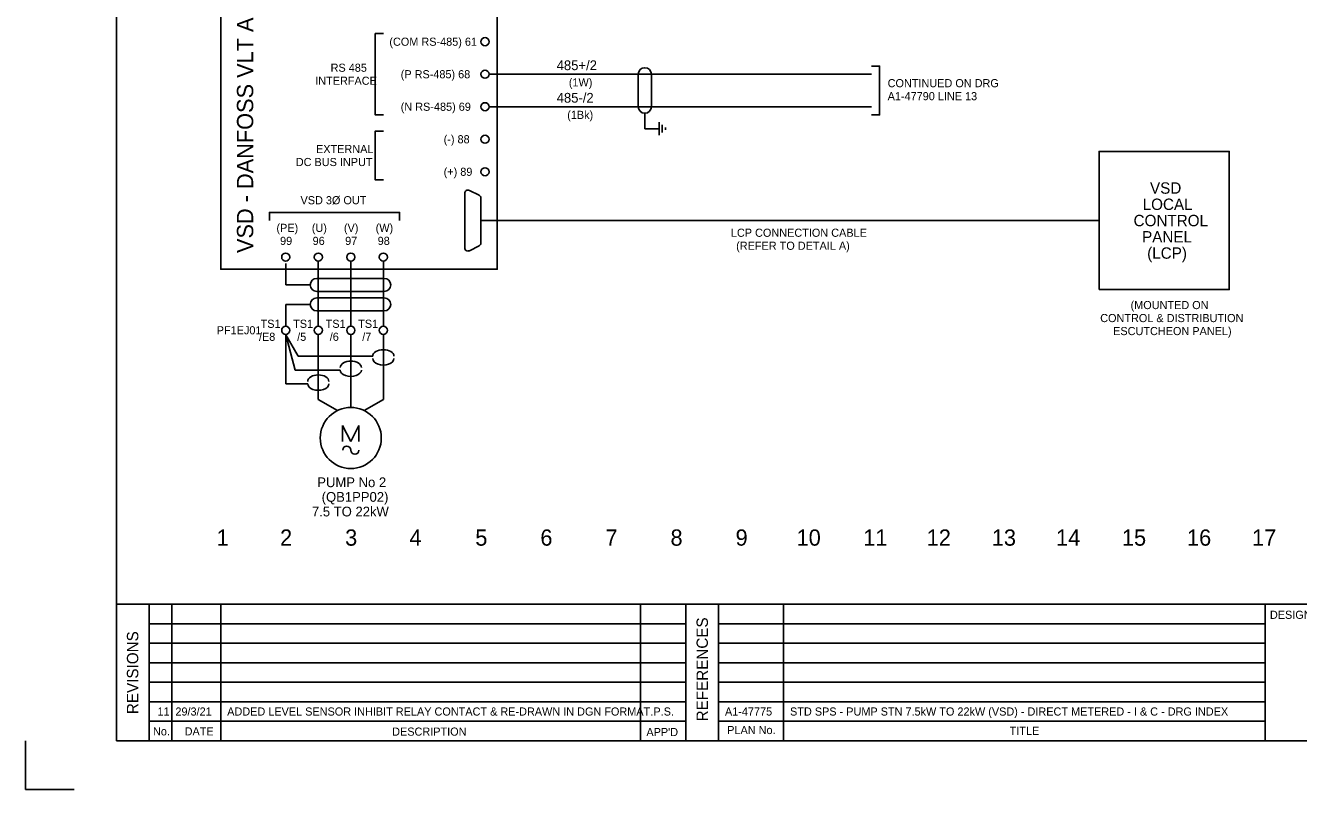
# Model space of a CAD drawing. Extents: x 0 to 841, y 0 to 594.
# Drawn here: x 0 to 391.3, y 0 to 235 of the extents above; entities that cross this region are included whole.
import ezdxf

# ---------------------------------------------------------------- set-up
doc = ezdxf.new("R2010")
doc.units = 0
for name, color, linetype in [('A1BORDER', 7, 'Continuous'), ('BASE', 7, 'Continuous'), ('Level 1', 7, 'Continuous'), ('Level 10', 7, 'Continuous'), ('Level 4', 7, 'Continuous'), ('Level 5', 7, 'Continuous'), ('Level 6', 7, 'Continuous'), ('Screen', 7, 'Continuous')]:
    doc.layers.add(name, color=color, linetype=linetype)

msp = doc.modelspace()

# ---------------------------------------------------------------- linework, layer by layer
at = {"layer": 'A1BORDER'}
for p, q in [((28, 581), (28, 15)), ((28, 57), (829, 57)), ((38, 15), (38, 57)), ((45, 15), (45, 57)), ((60, 15), (60, 57)), ((189, 15), (189, 57)), ((203, 15), (203, 57)), ((213, 15), (213, 57)), ((233, 15), (233, 57)), ((381, 15), (381, 57)), ((203, 51), (38, 51)), ((213, 51), (381, 51)), ((203, 45), (38, 45)), ((213, 45), (381, 45)), ((203, 39), (38, 39)), ((213, 39), (381, 39)), ((203, 33), (38, 33)), ((213, 33), (381, 33)), ((38, 27), (203, 27)), ((213, 27), (381, 27)), ((203, 21), (38, 21)), ((213, 21), (381, 21)), ((0, 0), (0, 15)), ((829, 15), (28, 15)), ((0, 0), (15, 0))]:
    msp.add_line(p, q, dxfattribs=at)
at = {"layer": 'BASE'}
for p, q in [((188.37, 220), (188.37, 210)), ((192.37, 220), (192.37, 210)), ((190.37, 208), (190.37, 203.25)), ((194.74, 203.25), (190.37, 203.25))]:
    msp.add_line(p, q, dxfattribs=at)
for centre, start, end in [((190.37, 220), 0, 180), ((190.37, 210), 180, 0)]:
    msp.add_arc(centre, 2, start, end, dxfattribs=at)
at = {"layer": 'Level 1'}
for p, q in [((136.45, 184.28), (139.45, 182.78)), ((135, 166.62), (135, 183.38)), ((140, 168.12), (140, 181.88)), ((140, 175), (330, 175)), ((136.45, 165.72), (139.45, 167.22)), ((90, 162.5), (90, 142.5)), ((100, 142.5), (100, 162.5)), ((110, 162.5), (110, 142.5)), ((90, 140), (90, 120)), ((100, 117.5), (100, 140)), ((110, 140), (110, 120))]:
    msp.add_line(p, q, dxfattribs=at)
for points in [[(60, 480), (145, 480), (145, 160), (60, 160)], [(330, 153.75), (370, 153.75), (370, 196.25), (330, 196.25)]]:
    msp.add_lwpolyline(points, close=True, dxfattribs=at)
for points in [[(110, 207.5), (107.5, 207.5), (107.5, 232.5), (110, 232.5)], [(260, 222.5), (262.5, 222.5), (262.5, 207.5), (260, 207.5)], [(110, 202.5), (107.5, 202.5), (107.5, 187.5), (110, 187.5)], [(75, 175), (75, 177.5), (115, 177.5), (115, 175)]]:
    msp.add_lwpolyline(points, dxfattribs=at)
for centre, start, end in [((136, 183.38), 63.4349, 180), ((139, 181.88), 0, 63.4349), ((136, 166.62), 180, 296.5651), ((139, 168.12), 296.5651, 360)]:
    msp.add_arc(centre, 1, start, end, dxfattribs=at)
at = {"layer": 'Level 10'}
for p, q in [((194.74, 201.25), (194.74, 205.25)), ((195.74, 202.05), (195.74, 204.45)), ((196.74, 202.85), (196.74, 203.65))]:
    msp.add_line(p, q, dxfattribs=at)
at = {"layer": 'Level 4'}
for p, q in [((97.49, 112), (100, 107)), ((97.49, 107), (97.49, 112)), ((100, 107), (102.51, 112)), ((102.51, 112), (102.51, 107))]:
    msp.add_line(p, q, dxfattribs=at)
for centre, radius in [((80, 163.75), 1.25), ((90, 163.75), 1.25), ((100, 163.75), 1.25), ((110, 163.75), 1.25), ((80, 141.25), 1.25), ((90, 141.25), 1.25), ((100, 141.25), 1.25), ((110, 141.25), 1.25), ((100, 108.12), 9.38)]:
    msp.add_circle(centre, radius, dxfattribs=at)
for centre, start, end in [((98.75, 104.38), 0, 180), ((101.25, 104.38), 180, 360)]:
    msp.add_arc(centre, 1.24, start, end, dxfattribs=at)
at = {"layer": 'Level 5'}
for p, q in [((90, 120), (95.89, 116.61)), ((110, 120), (104.11, 116.61))]:
    msp.add_line(p, q, dxfattribs=at)
for centre in [(141.25, 230), (141.25, 220), (141.25, 210), (141.25, 200), (141.25, 190)]:
    msp.add_circle(centre, 1.25, dxfattribs=at)
at = {"layer": 'Level 6'}
for p, q in [((142.5, 220), (260, 220)), ((142.5, 210), (260, 210))]:
    msp.add_line(p, q, dxfattribs=at)
at = {"layer": 'Screen'}
for p, q in [((80, 155.21), (80, 161.82)), ((89.52, 157.21), (110.27, 157.21)), ((80, 155.21), (87.52, 155.21)), ((89.52, 153.21), (110.27, 153.21)), ((80, 149.21), (87.52, 149.21)), ((80, 142.37), (80, 149.21)), ((89.52, 151.21), (110.27, 151.21)), ((89.52, 147.21), (110.27, 147.21)), ((80, 139.87), (82.9, 129.03)), ((80, 124.78), (80, 139.87)), ((80, 139.87), (83.8, 133.28)), ((83.8, 133.28), (106.75, 133.28)), ((82.9, 129.03), (96.75, 129.03)), ((80, 124.78), (86.75, 124.78))]:
    msp.add_line(p, q, dxfattribs=at)
for centre, start, end in [((89.52, 155.21), 90, 270), ((110.27, 155.21), 270, 90), ((89.52, 149.21), 90, 270), ((110.27, 149.21), 270, 90)]:
    msp.add_arc(centre, 2, start, end, dxfattribs=at)
for centre, start_param, end_param in [((110, 133.28), 3.141593, 6.283185), ((100, 129.78), 3.141593, 6.283185), ((110, 132.53), 0, 3.141593), ((90, 125.53), 3.141593, 6.283185), ((100, 129.03), 0, 3.141593), ((90, 124.78), 0, 3.141593)]:
    msp.add_ellipse(centre, major_axis=(-3.25, 0), ratio=0.615385, start_param=start_param, end_param=end_param, dxfattribs=at)

# ---------------------------------------------------------------- texts
at = {"layer": 'A1BORDER'}
for s, p in [('DESIGNED BY:', (382.5, 52.5)), ('No.', (39.21, 16.65)), ('DATE', (48.92, 16.65)), ('DESCRIPTION', (112.71, 16.57)), ("APP'D", (190.85, 16.44)), ('PLAN No.', (215.69, 17.06)), ('TITLE', (302.5, 16.81))]:
    msp.add_text(s, height=2.5, dxfattribs=at).set_placement(p)
for s, p in [('REFERENCES', (209.76, 20.96)), ('REVISIONS', (34.68, 23.2))]:
    msp.add_text(s, height=3.5, rotation=90, dxfattribs=at).set_placement(p)
at = {"layer": 'Level 1'}
msp.add_text('VSD - DANFOSS VLT AQUA FC 202', height=5, rotation=90, dxfattribs=at).set_placement((70, 165))
for s, height, p in [('(COM RS-485) 61', 2.5, (111.85, 228.75)), ('RS 485', 2.5, (93.79, 220.75)), ('INTERFACE', 2.5, (89.06, 216.75)), ('(P RS-485) 68', 2.5, (115.34, 218.75)), ('CONTINUED ON DRG', 2.5, (265, 216)), ('(N RS-485) 69', 2.5, (115.34, 208.75)), ('A1-47790 LINE 13', 2.5, (265, 212)), ('(-) 88', 2.5, (128.54, 198.75)), ('EXTERNAL', 2.5, (89.31, 195.75)), ('DC BUS INPUT', 2.5, (83.09, 191.75)), ('(+) 89', 2.5, (128.54, 188.75)), ('VSD', 3.5, (345.64, 183.25)), ('VSD 3Ø OUT', 2.5, (84.54, 180)), ('LOCAL', 3.5, (343.38, 178.25)), ('CONTROL', 3.5, (340.59, 173.25)), ('(PE)', 2.5, (77.14, 171.5)), ('(U)', 2.5, (88.01, 171.5)), ('(V)', 2.5, (97.88, 171.5)), ('(W)', 2.5, (107.64, 171.5)), ('LCP CONNECTION CABLE', 2.5, (216.82, 170)), ('99', 2.5, (78.26, 167.5)), ('96', 2.5, (88.26, 167.5)), ('97', 2.5, (98.26, 167.5)), ('98', 2.5, (108.26, 167.5)), ('(REFER TO DETAIL A)', 2.5, (218.44, 166)), ('PANEL', 3.5, (343.2, 168.25)), ('(LCP)', 3.5, (344.77, 163.25)), ('(MOUNTED ON', 2.5, (339.67, 147.76)), ('CONTROL & DISTRIBUTION', 2.5, (330.33, 143.76)), ('ESCUTCHEON PANEL)', 2.5, (334.31, 139.76)), ('PUMP No 2', 3, (89.69, 93)), ('(QB1PP02)', 3, (91.04, 88.5)), ('7.5 TO 22kW', 3, (88.05, 84)), ('1', 5, (58.76, 75)), ('2', 5, (78.26, 75)), ('3', 5, (98.26, 75)), ('4', 5, (118.01, 75)), ('5', 5, (138.26, 75)), ('6', 5, (158.26, 75)), ('7', 5, (178.26, 75)), ('8', 5, (198.26, 75)), ('9', 5, (218.26, 75)), ('10', 5, (237.01, 75)), ('11', 5, (257.51, 75)), ('12', 5, (277.01, 75)), ('13', 5, (297.01, 75)), ('14', 5, (316.77, 75)), ('15', 5, (337.01, 75)), ('16', 5, (357.01, 75)), ('17', 5, (377.01, 75)), ('11', 2.5, (40.57, 22.75)), ('29/3/21', 2.5, (46.09, 22.75)), ('ADDED LEVEL SENSOR INHIBIT RELAY CONTACT & RE-DRAWN IN DGN FORMAT.', 2.5, (62, 22.75)), ('P.S.', 2.5, (193.02, 22.75)), ('A1-47775', 2.5, (215, 22.75)), ('STD SPS - PUMP STN 7.5kW TO 22kW (VSD) - DIRECT METERED - I & C - DRG INDEX', 2.5, (235, 22.75))]:
    msp.add_text(s, height=height, dxfattribs=at).set_placement(p)
at = {"layer": 'Level 5'}
for s, height, p in [('485+/2', 3, (163.27, 221.25)), ('(1W)', 2.5, (167.01, 216.25)), ('485-/2', 3, (163.27, 211.25)), ('(1Bk)', 2.5, (166.51, 206.25))]:
    msp.add_text(s, height=height, dxfattribs=at).set_placement(p)
at = {"layer": 'Level 6'}
for s, p in [('PF1EJ01', (58.79, 140)), ('TS1', (72.27, 142)), ('TS1', (82.27, 142)), ('TS1', (92.27, 142)), ('TS1', (102.27, 142)), ('/E8', (71.77, 138)), ('/5', (83.52, 138)), ('/6', (93.52, 138)), ('/7', (103.52, 138))]:
    msp.add_text(s, height=2.5, dxfattribs=at).set_placement(p)

doc.saveas('drawing.dxf')
